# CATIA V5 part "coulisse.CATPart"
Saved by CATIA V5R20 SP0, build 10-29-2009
Part number: coulisse
Bounding box of the stored display mesh (mm): x 0 to 5, y -10.996 to 192.596, z -101.864 to 68.634
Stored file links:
  C:\Users\thinkmotion1\Desktop\IAO OK\IAO_2010_1458_splanchena\Correction_Khaled\coulisse.CATPart
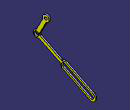
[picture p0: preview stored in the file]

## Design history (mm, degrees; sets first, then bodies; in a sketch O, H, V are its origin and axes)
Body1 (main body)
  Sketch1 on yz-plane, origin (0, 0, 0), H (0, 1, 0), V (0, 0, 1)
    arc A1 centre (0, 0) radius 11 from (10.995, 0.3312) to (9.6093, 5.3536) ccw
    circle A2 centre (0, 0) radius 7.5
    line L1 (6.5076, -8.8685) -> (76.6125, -43.0636)
    line L2 (10.995, 0.3312) -> (80.7942, -34.4836)
    line L3 (76.6125, -43.0636) -> (83.3995, -55.3085)
    line L4 (80.7942, -34.4836) -> (94.6407, -32.4166)
    line L5 (83.3995, -55.3085) -> (174.8005, -100.5838)
    point P7 (174.8005, -100.5838)
    line L6 (94.6407, -32.4166) -> (185.6601, -78.4543)
    arc A3 centre (180.2714, -89.5392) radius 12.3253 from (185.6601, -78.4543) to (174.8005, -100.5838) cw
    point P10 (174.8005, -100.5838)
    line L7 (86.0627, -49.932) -> (177.4638, -95.2072)
    line L8 (91.9326, -37.7706) -> (182.952, -83.8083)
    point P13 (91.9326, -37.7706)
    arc A4 centre (180.2718, -89.5385) radius 6.3261 from (182.952, -83.8083) to (177.4638, -95.2072) cw
    arc A5 centre (89.0599, -43.8813) radius 6.7523 from (91.9326, -37.7706) to (86.0627, -49.932) ccw
    point P17 (91.9326, -37.7706)
    arc A6 centre (30.4203, 57.6455) radius 11 from (31.4238, 46.6914) to (20.8109, 52.292) ccw
    circle A7 centre (30.4203, 57.6455) radius 4.25
    line L9 (-1.0036, 10.9541) -> (20.8109, 52.292)
    point P19 (-1.0036, 10.9541)
    line L10 (9.6093, 5.3536) -> (31.4238, 46.6914)
    arc A8 centre (0, 0) radius 11 from (-1.0036, 10.9541) to (6.5076, -8.8685) ccw
    radius A1 = 11
    radius A2 = 7.5
    length L2 = 78
    length L1 = 78
    length L6 = 102
    length L5 = 102
    distance L8 L6 = 6
    distance L7 L5 = 6
    radius A6 = 11
    radius A7 = 4.25
    coincidence: P10 L5, P7 P10, P13 P17, P19 A1, A1 A8
    tangency: A3 L5, A4 L7, A5 L7
  Pad1: profile Sketch1, direction (1, 0, 0), length 5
